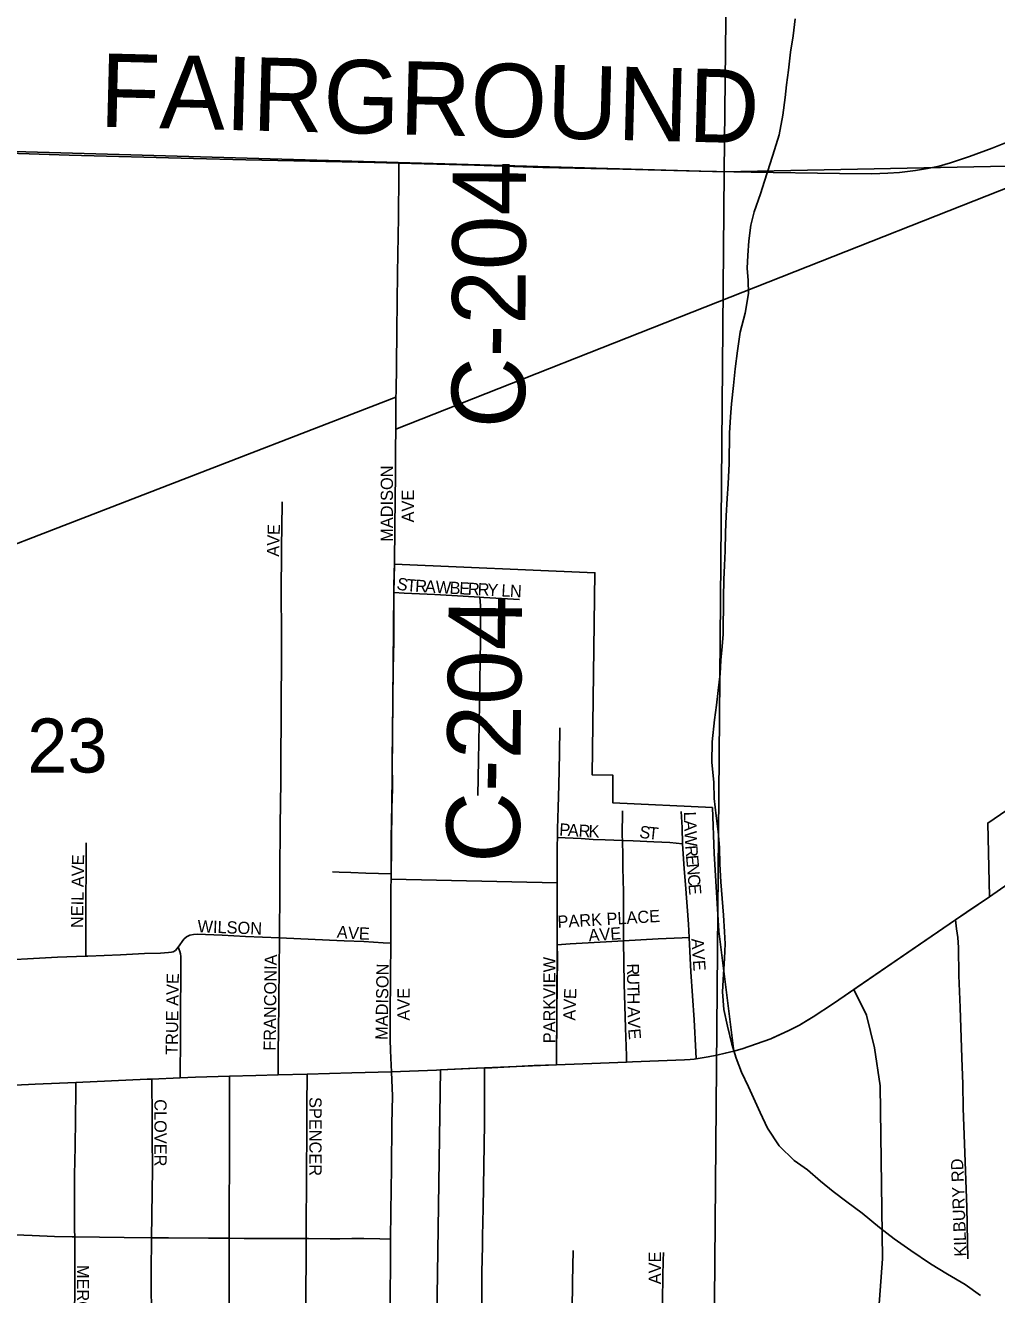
# Model space of a CAD drawing. Extents: x 1584893 to 1934202, y 663575 to 1091909.
# Drawn here: x 1800974 to 1804945, y 942980 to 948170 of the extents above; entities that cross this region are included whole.
import ezdxf

# ---------------------------------------------------------------- set-up
doc = ezdxf.new("R2010")
doc.units = 0
for name, color, linetype in [('GM_X_City_Street', 7, 'Continuous'), ('GM_X_City_Street_Text', 7, 'Continuous'), ('GM_X_Corporation', 7, 'Continuous'), ('GM_X_County_Road', 7, 'Continuous'), ('GM_X_County_Road_Text', 7, 'Continuous'), ('GM_X_Minor_River', 7, 'Continuous'), ('GM_X_Section', 7, 'Continuous'), ('GM_X_Section_Text', 7, 'Continuous'), ('GM_X_State_Route', 7, 'Continuous'), ('GM_X_Township_Subdivision', 7, 'Continuous'), ('GM_X_Township_Subdivision_Text', 7, 'Continuous')]:
    doc.layers.add(name, color=color, linetype=linetype)

msp = doc.modelspace()

# ---------------------------------------------------------------- linework, layer by layer
at = {"layer": 'GM_X_City_Street'}
for points in [[(1802482.4, 945967), (1802484.7, 946120.6), (1802487.3, 946335.9), (1802487.1, 946435.3), (1802488.3, 946519.1)], [(1802012.7, 944438.7), (1802013, 944462.1), (1802013.4, 944614.7), (1802013.7, 944704), (1802016.1, 944899.8), (1802017.6, 945076.3), (1802018.8, 945232.8), (1802019.3, 945280.4), (1802019.8, 945340), (1802019.2, 945393.3), (1802019.7, 945452.5), (1802020.2, 945525), (1802020.5, 945696.2), (1802019.9, 945840.2), (1802019.7, 945888.4), (1802020.7, 945982.1), (1802021.4, 946044.3), (1802022.2, 946114.3), (1802023.3, 946221.2)], [(1801220.2, 944363.7), (1801220.2, 944385.3), (1801220.4, 944415.1), (1801220.6, 944449), (1801220.8, 944492.6), (1801221.2, 944559), (1801221.5, 944626.8), (1801221.8, 944687), (1801222.1, 944737.5), (1801222.3, 944781.1), (1801222.6, 944827.4)], [(1802228.8, 944709.1), (1802256.4, 944707.5), (1802303.7, 944706.6), (1802365.1, 944704), (1802468.6, 944700.5)], [(1802467.3, 944417.3), (1802467.8, 944512), (1802467.8, 944574.3), (1802467.8, 944621.6), (1802468.6, 944700.5)], [(1801598, 944401.1), (1801621.8, 944433.2), (1801632.4, 944443.4), (1801645.6, 944449.6), (1801661, 944452.3), (1801676.9, 944453.5), (1801709.5, 944452.8), (1801778.6, 944449.4), (1801873.3, 944444.9), (1802012.7, 944438.7)], [(1802007.1, 943878.3), (1802007.3, 943916.9), (1802007.5, 943948), (1802007.6, 943966.5), (1802008.1, 944065.9), (1802009.3, 944160.8), (1802010, 944221.1), (1802010.8, 944280.4), (1802011.7, 944352.3), (1802012.2, 944396), (1802012.7, 944438.7)], [(1802012.7, 944438.7), (1802217.5, 944429.3), (1802277.5, 944426.9), (1802357.3, 944423.4), (1802436.2, 944419), (1802467.3, 944417.3)], [(1802470.5, 943891.6), (1802469.1, 943918.4), (1802466.9, 943978.2), (1802465.3, 944022.7), (1802465.2, 944113.8), (1802466.9, 944285.7), (1802467.3, 944417.3)], [(1801220.2, 944363.7), (1801229, 944364.1), (1801362.3, 944368.8), (1801460.5, 944374.9), (1801526, 944376.9), (1801559.4, 944378.7), (1801570.8, 944379.8), (1801577.8, 944381.5), (1801587.4, 944387.8), (1801592.7, 944393.9), (1801598, 944401.1)], [(1801606.7, 943866.2), (1801606.9, 943907.1), (1801607.4, 943994.5), (1801607.7, 944046), (1801608, 944113.1), (1801608.4, 944185), (1801608.8, 944243.4), (1801609, 944294.9), (1801609.3, 944336.7), (1801609.4, 944362.1), (1801607.6, 944373.8), (1801605.1, 944382.9), (1801600.7, 944394.1), (1801598, 944401.1)], [(1800931.6, 944350.1), (1800982.9, 944352.7), (1801104.7, 944359.7), (1801220.2, 944363.7)], [(1801179.9, 943847.9), (1801179.6, 943812.8), (1801177, 943584.5), (1801175.1, 943470), (1801174.8, 943341.1), (1801175.2, 943245.2), (1801175.4, 943215.9)], [(1801489.5, 943212.5), (1801490.5, 943303), (1801492.8, 943496), (1801492, 943620.5), (1801492.4, 943685.9), (1801492.4, 943734.5), (1801490.8, 943827), (1801490.1, 943861.3)], [(1801806.7, 943210.3), (1801807.4, 943353.3), (1801807.7, 943506.1), (1801807.8, 943569.5), (1801807.9, 943652), (1801808.3, 943833.1), (1801808.4, 943872.7)], [(1802125.3, 943881.8), (1802125.2, 943852), (1802124.8, 943779), (1802124.3, 943693.1), (1802123.9, 943591.5), (1802123.6, 943534.2), (1802123, 943419.6), (1802121.8, 943288.1), (1802121.8, 943271.7), (1802122.1, 943209)], [(1802467, 943207), (1802468.1, 943319.1), (1802470.5, 943498.5), (1802472.6, 943677.9), (1802474.4, 943791.9), (1802470.5, 943891.6)], [(1800829.3, 943229.2), (1801001.3, 943221.1), (1801093.2, 943217), (1801165, 943216.1), (1801175.4, 943215.9)], [(1801175.4, 943215.9), (1801175.7, 943180.5), (1801175.9, 943016.8), (1801174.5, 942886), (1801173.5, 942689.7), (1801172.3, 942559.6), (1801171.3, 942463.8), (1801170.6, 942382.7), (1801168.5, 942314.6)], [(1801175.4, 943215.9), (1801378.1, 943213.6), (1801489.5, 943212.5)], [(1801482.9, 942294.7), (1801482.9, 942300.6), (1801483.2, 942332.4), (1801486.3, 942676.2), (1801489.4, 942938), (1801488.3, 942987.2), (1801488.3, 943085.6), (1801489.3, 943200.3), (1801489.5, 943212.5)], [(1801489.5, 943212.5), (1801558.3, 943211.9), (1801722.1, 943211.5), (1801806.7, 943210.3)], [(1801800.9, 942275.1), (1801801.6, 942348.8), (1801803.9, 942589.5), (1801805.3, 942802.3), (1801806.4, 943031.4), (1801806.5, 943173.6), (1801806.7, 943210.3)], [(1801806.7, 943210.3), (1801868.4, 943209.2), (1801918.3, 943209.7), (1801967.1, 943209.3), (1802122.1, 943209)], [(1802122.1, 943209), (1802122.1, 943189.8), (1802121.7, 943156.9), (1802121.8, 943124.1), (1802121.4, 943074.8), (1802120.9, 943043.6), (1802120, 942971.6), (1802119.8, 942923.8), (1802119.4, 942867.4), (1802119.2, 942829.2), (1802118.9, 942762.5), (1802118, 942532.3), (1802116.8, 942422.8), (1802116.1, 942384.6), (1802114.8, 942317.8), (1802113.4, 942262.2), (1802113.1, 942251.9)], [(1802122.1, 943209), (1802130.6, 943209), (1802219.9, 943208.7), (1802260, 943208.7), (1802308.4, 943208.9), (1802357.1, 943209.2), (1802422.7, 943207.9), (1802467, 943207)], [(1802455.2, 942220.6), (1802456.3, 942285.9), (1802457.6, 942363), (1802458.3, 942477.3), (1802460.1, 942591.4), (1802460.9, 942671.8), (1802461.1, 942734.1), (1802461.6, 942749.5), (1802463.4, 942879), (1802465.6, 942976.5), (1802466.2, 943106.9), (1802467, 943207)]]:
    msp.add_lwpolyline(points, dxfattribs=at)
at = {"layer": 'GM_X_Corporation'}
for points in [[(1800456.1, 945864.7), (1802488.6, 946649.4), (1802488.3, 946519.1), (1805222.2, 947597.8)], [(1805012.7, 944979.3), (1804908.7, 944908.4), (1804915.8, 944607.2), (1804776.9, 944512.7), (1804277.6, 944170), (1804195.2, 944115.6), (1804166.8, 944098.9), (1804138.5, 944082.2), (1804094.8, 944059.4), (1804030.3, 944029.7), (1804021.1, 944025.4), (1803962.8, 944005.1), (1803904.4, 943984.7), (1803870.9, 943975.3), (1803808.8, 944465.8), (1803789.5, 944784.1), (1803782.7, 944971.5), (1803375.3, 944991.1), (1803375.6, 945103.5), (1803291.5, 945104.8), (1803302.1, 945931.7), (1802482.3, 945967), (1802480.7, 945850.9), (1802469.4, 944679.3), (1803147.3, 944663.8), (1803148.2, 944410.3), (1803145.2, 943920.2), (1802850.8, 943906.8), (1802671.4, 943898.9), (1802646.7, 942233.9)]]:
    msp.add_lwpolyline(points, dxfattribs=at)
at = {"layer": 'GM_X_County_Road'}
for points in [[(1802501.2, 947606), (1802809.9, 947597.9), (1803088.7, 947589.4), (1803416.9, 947582.6), (1803728.6, 947573.8), (1803941.8, 947569.7), (1804302.8, 947564.2), (1804434, 947563.3), (1804499.4, 947565.2), (1804548.3, 947568.6), (1804613.2, 947576.5), (1804661.5, 947584.5), (1804709.3, 947595), (1804756.6, 947607.9), (1804834.3, 947633.3), (1804926.5, 947667.5), (1805185.3, 947771.7)], [(1799836.2, 947683), (1800250.7, 947669.5), (1800595.1, 947657.6), (1800988.9, 947645), (1801152.8, 947639.2), (1801661.5, 947625.6), (1801874.7, 947619.8), (1802137.2, 947614.3), (1802399.7, 947608.7), (1802501.2, 947606)], [(1802488.6, 946649.5), (1802489.1, 946670.9), (1802490.6, 946779.1), (1802492.1, 946922.1), (1802494.6, 947156.3), (1802498.6, 947386.1), (1802500.6, 947560.7), (1802501.2, 947606)], [(1802488.3, 946519.1), (1802488.8, 946569.7), (1802488.8, 946639.6), (1802488.6, 946649.5)], [(1802480.7, 945850.9), (1802480.7, 945870.8), (1802481.6, 945936.9), (1802482.4, 945967)], [(1802468.6, 944700.5), (1802468.6, 944758.4), (1802469.5, 944831.2), (1802471.2, 944927.7), (1802474.2, 945047.6), (1802473.7, 945162.7), (1802474.6, 945278.5), (1802476.3, 945409.2), (1802478.1, 945537.2), (1802479.8, 945653.9), (1802480.7, 945788.5), (1802480.7, 945850.9)], [(1803891.7, 941145.1), (1803928.3, 941217.2), (1803997.2, 941317), (1804082, 941418.3), (1804141.9, 941520.2), (1804178.7, 941604.2), (1804203.7, 941699.2), (1804215.1, 941797.4), (1804218, 941909.9), (1804219.7, 942007.6), (1804214.9, 942210.2), (1804224.2, 942350.1), (1804253.3, 942479.3), (1804311.7, 942589.7), (1804403, 942735.4), (1804458.4, 942867.1), (1804477.6, 943126.6), (1804468.5, 943833.4), (1804445.6, 943988.5), (1804413.1, 944123), (1804361.2, 944227.4)]]:
    msp.add_lwpolyline(points, dxfattribs=at)
at = {"layer": 'GM_X_Minor_River'}
for points in [[(1803916.1, 946993.2), (1803930.4, 947073.1), (1803928.6, 947127.2), (1803924.8, 947177.2), (1803927, 947229.2), (1803931.2, 947289.3), (1803939.5, 947353.3), (1803953.7, 947407.2), (1803980, 947481.2), (1803996.2, 947533.2), (1804018.5, 947605.1), (1804036.7, 947661.1), (1804055, 947723), (1804071.3, 947803), (1804079.6, 947875), (1804085.8, 947927), (1804094, 947987), (1804102.3, 948061), (1804112.5, 948127), (1804120.8, 948197.1)], [(1804879.5, 942977.1), (1804815.6, 943021.4), (1804743.7, 943063.7), (1804673.8, 943106), (1804594, 943160.3), (1804526.1, 943208.6), (1804466.2, 943254.9), (1804394.4, 943313.2), (1804332.5, 943359.4), (1804276.6, 943401.7), (1804224.8, 943443.9), (1804170.9, 943490.1), (1804117, 943528.4), (1804055.2, 943588.6), (1804007.4, 943660.9), (1803977.6, 943725), (1803930, 943829.2), (1803902.2, 943889.4), (1803880.4, 943947.5), (1803862.6, 944003.6), (1803844.9, 944077.7), (1803829.1, 944145.8), (1803823.4, 944217.9), (1803827.7, 944289.9), (1803831.9, 944353.9), (1803834.2, 944414), (1803832.3, 944464), (1803828.6, 944532.1), (1803817.1, 944668.2), (1803813.4, 944740.2), (1803811.6, 944808.3), (1803805.9, 944874.3), (1803798.1, 944938.4), (1803790.4, 945008.5), (1803788.6, 945074.5), (1803780.9, 945156.6), (1803781.3, 945240.7), (1803791.6, 945330.7), (1803799.9, 945390.7), (1803806.1, 945450.7), (1803814.3, 945518.7), (1803816.6, 945574.7), (1803822.8, 945630.7), (1803827, 945680.7), (1803827.5, 945828.8), (1803829.8, 945904.8), (1803832.1, 945960.9), (1803834.3, 946020.9), (1803836.6, 946096.9), (1803838.8, 946165), (1803843.1, 946235), (1803847.3, 946295), (1803851.7, 946379), (1803852.1, 946503.1), (1803856.4, 946569.1), (1803860.6, 946623.1), (1803868.9, 946697.2), (1803875.2, 946765.2), (1803885.4, 946839.2), (1803895.7, 946915.2), (1803916.1, 946993.2)]]:
    msp.add_lwpolyline(points, dxfattribs=at)
at = {"layer": 'GM_X_Section'}
for points in [[(1798546, 953053.1), (1803891.8, 953170.2), (1803831.3, 947571.5), (1798501.2, 947724.3)], [(1803891.8, 953170.2), (1809287.5, 952939), (1809214, 947834.3), (1809209.1, 947678.4), (1803831.3, 947571.5)], [(1803831.3, 947571.5), (1803783.9, 942158.7), (1798488.5, 942423.4), (1798501.2, 947724.3)], [(1809209.1, 947678.4), (1809163.3, 942525.6), (1803783.9, 942158.7), (1803831.3, 947571.5)]]:
    msp.add_lwpolyline(points, close=True, dxfattribs=at)
at = {"layer": 'GM_X_State_Route'}
for points in [[(1804915.8, 944607.2), (1805023.7, 944681.7)], [(1803870.9, 943975.3), (1803904.4, 943984.8), (1804021.1, 944025.4), (1804094.8, 944059.4), (1804138.5, 944082.2), (1804195.1, 944115.6), (1804277.6, 944170), (1804361.2, 944227.4), (1804375, 944236.9), (1804776.9, 944512.7), (1804820.4, 944542.6), (1804915.8, 944607.2)], [(1803145.2, 943920.2), (1803325.1, 943926.3), (1803431.6, 943930.7), (1803455.9, 943931.7), (1803668.4, 943940.3), (1803691.1, 943941.9), (1803708.1, 943943.4), (1803715.7, 943944.4), (1803740.3, 943947.7), (1803765.3, 943951.7), (1803800.6, 943959.1), (1803835.5, 943966.8), (1803870.9, 943975.3)], [(1800931, 943836.8), (1801013.3, 943840.8), (1801179.9, 943847.9), (1801472.2, 943860.5), (1801490.1, 943861.3), (1801606.7, 943866.2), (1801668.7, 943868.9), (1801808.4, 943872.7), (1801915.3, 943875.6), (1802007.1, 943878.3), (1802125.3, 943881.8), (1802308.9, 943887.2), (1802470.5, 943891.6), (1802654.9, 943898.1), (1802671.4, 943898.9)], [(1802671.4, 943898.9), (1802785.4, 943904.2), (1802850.8, 943906.8), (1802880.4, 943908), (1803054.2, 943917), (1803145.2, 943920.2)]]:
    msp.add_lwpolyline(points, dxfattribs=at)
at = {"layer": 'GM_X_Township_Subdivision'}
for points in [[(1802480.7, 945850.9), (1802522.1, 945848.8), (1802647.6, 945842.3), (1802717.5, 945839.1), (1802832.2, 945831.6)], [(1802824, 945020.4), (1802825.9, 945165.9), (1802829.3, 945312.6), (1802833, 945573.7), (1802834.4, 945654), (1802835, 945716.4), (1802834.4, 945764.4), (1802834.1, 945796.8), (1802832.2, 945831.6)], [(1802832.2, 945831.6), (1802847.6, 945830.6), (1802993.9, 945822.8)], [(1803149.2, 944849.3), (1803149.9, 944885.2), (1803152.5, 944971.4), (1803154.4, 945062.9), (1803157.3, 945193), (1803158.9, 945297.5)], [(1803414.8, 944837.4), (1803413.9, 944855.9), (1803415.2, 944958.8)], [(1803660.7, 944823.3), (1803658.7, 944889.7), (1803654.4, 944955.3)], [(1803147.3, 944663.8), (1803148.6, 944816.6), (1803149.2, 944849.3)], [(1803149.2, 944849.3), (1803180.5, 944847.3), (1803246, 944844.5), (1803295, 944841.7), (1803344, 944839.5), (1803414.8, 944837.4)], [(1803419.3, 944426.9), (1803419.2, 944545.9), (1803418.8, 944578), (1803418.8, 944627.1), (1803416.8, 944725.1), (1803415.8, 944774.2), (1803414.8, 944837.4)], [(1803414.8, 944837.4), (1803458.4, 944836), (1803543.2, 944832), (1803608.6, 944828.1), (1803660.7, 944823.3)], [(1803687.3, 944440.8), (1803684.4, 944495.2), (1803673, 944657.7), (1803667.9, 944721.4), (1803660.7, 944823.3)], [(1803148.2, 944410.3), (1803147.3, 944663.8)], [(1804827.1, 943125.9), (1804823.2, 943338.2), (1804813.3, 943597), (1804808.3, 943742.5), (1804806, 943840.2), (1804802.8, 943947.9), (1804796.2, 944153.7), (1804790.9, 944285.1), (1804788.3, 944399.4), (1804785.7, 944440.6), (1804781.3, 944476.2), (1804776.9, 944512.7)], [(1803148.2, 944410.3), (1803200.5, 944414.2), (1803347.9, 944423.1), (1803419.3, 944426.9)], [(1803419.3, 944426.9), (1803561.1, 944434.3), (1803658.8, 944439.3), (1803687.3, 944440.8)], [(1803431.6, 943930.7), (1803430.8, 943956.2), (1803427.3, 944070.4), (1803422, 944250.5), (1803419.3, 944426.9)], [(1803715.7, 943944.4), (1803714.3, 943973), (1803707.7, 944103.2), (1803694.8, 944299.4), (1803687.3, 944440.8)], [(1803145.2, 943920.2), (1803146.8, 944132.4), (1803149.3, 944359.3), (1803148.2, 944410.3)], [(1802842.4, 943177.8), (1802843.3, 943219), (1802844.9, 943334), (1802850.5, 943679.3), (1802851.2, 943745.1), (1802850.9, 943843.8), (1802850.8, 943863.5), (1802850.8, 943906.8)], [(1802833.4, 942401.2), (1802833.3, 942430.8), (1802834.8, 942529.4), (1802834.4, 942578.8), (1802835.9, 942627.8), (1802838.2, 942792.2), (1802838.3, 942825.1), (1802839.9, 942989.4), (1802840.5, 943038.8), (1802840.2, 943071.8), (1802842.4, 943177.8)], [(1803205.1, 942393.7), (1803205.5, 942428), (1803208, 942671.6), (1803209.9, 942913.3), (1803211.2, 943032.9), (1803213.7, 943159.9)], [(1803561.9, 942408.7), (1803570.4, 942423), (1803573, 942437.1), (1803574.9, 942468.8), (1803576.7, 942647.4), (1803578.9, 942956.4), (1803580.1, 943053.8), (1803580.8, 943119), (1803582.4, 943151.6)]]:
    msp.add_lwpolyline(points, dxfattribs=at)

# ---------------------------------------------------------------- texts
at = {"layer": 'GM_X_City_Street_Text'}
for s, rotation, p in [('MADISON', 90, (1802476.6, 946058.3)), ('AVE', 90, (1802562.7, 946137.5)), ('V', 87.9324, (1802011.9, 946041)), ('E', 88.323, (1802013.5, 946085.4)), ('A', 87.9234, (1802010.3, 945997.1)), ('NEIL AVE', 89.1065, (1801209.5, 944478.5)), ('WILSON', 357.8737, (1801677, 944461.7)), ('A', 354.3068, (1802245.5, 944439.6)), ('V', 356.863, (1802291.7, 944435.1)), ('E', 357.2782, (1802336.1, 944432.6)), ('FRANCONIA', 89.3024, (1801997.1, 943976.9)), ('MADISON', 89.118, (1802454.7, 944021.3)), ('TRUE AVE', 89.1777, (1801596.6, 943959.8)), ('AVE', 90, (1802545.1, 944100.3)), ('CLOVER', 270, (1801501.1, 943779.1)), ('SPENCER', 270, (1802134.7, 943787.9)), ('MERCHANT', 270, (1801184.3, 943101.5))]:
    msp.add_text(s, height=50, rotation=rotation, dxfattribs=at).set_placement(p)
at = {"layer": 'GM_X_County_Road_Text'}
for s, rotation, p in [('FAIRGROUND', 358.5316, (1801275.4, 947756)), ('C-204', 89.724, (1803016.1, 946522.1)), ('C-204', 89.4594, (1802994.1, 944743.9))]:
    msp.add_text(s, height=300, rotation=rotation, dxfattribs=at).set_placement(p)
at = {"layer": 'GM_X_Section_Text'}
msp.add_text('23', height=221, rotation=0, dxfattribs=at).set_placement((1800981.3, 945114.8))
at = {"layer": 'GM_X_Township_Subdivision_Text'}
for s, rotation, p in [('S', 348.2239, (1802488.8, 945864.9)), ('T', 355.7348, (1802530.4, 945856.7)), ('R', 356.6891, (1802566.4, 945854)), ('A', 356.784, (1802606, 945851.8)), ('W', 356.7835, (1802649.9, 945849.3)), ('B', 356.7966, (1802707, 945846.1)), ('E', 356.802, (1802746.6, 945843.9)), ('R', 356.7932, (1802781.7, 945841.9)), ('R', 357.76, (1802822.2, 945839.7)), ('Y', 357.0263, (1802861.6, 945838.1)), ('L', 356.993, (1802918.7, 945835.1)), ('N', 356.9826, (1802953.8, 945833.3)), ('L', 271.9401, (1803665.9, 944954.2)), ('P', 356.5276, (1803155.5, 944857.7)), ('A', 356.5474, (1803190.6, 944855.5)), ('R', 356.558, (1803234.5, 944852.9)), ('K', 358.0675, (1803275.5, 944850.4)), ('S', 352.1635, (1803481.9, 944848.8)), ('T', 354.1484, (1803518.6, 944843.8)), ('A', 271.9538, (1803667, 944919)), ('W', 272.4661, (1803668.5, 944874.6)), ('R', 274.5668, (1803671.1, 944815.4)), ('E', 274.9694, (1803674.3, 944775.5)), ('N', 274.9669, (1803677.4, 944740.5)), ('C', 274.9613, (1803681.2, 944696.6)), ('E', 274.9569, (1803684.6, 944657.2)), ('PARK PLACE', 3.3645, (1803150.8, 944479.3)), ('AVE', 3.9434, (1803277.7, 944424.2)), ('AVE', 273.9431, (1803696.6, 944435.4)), ('PARKVIEW', 90, (1803141, 944007.9)), ('R', 270.9714, (1803432.7, 944333.7)), ('U', 270.9953, (1803433.3, 944294)), ('E', 87.5128, (1803225.2, 944187.7)), ('T', 270.9835, (1803434.1, 944250.1)), ('H', 270.9618, (1803434.7, 944214.9)), ('V', 87.7697, (1803223.5, 944143.8)), ('A', 270.9618, (1803435.7, 944157.6)), ('A', 88.929, (1803222.7, 944100.1)), ('V', 271.8296, (1803436.4, 944112.8)), ('E', 274.9694, (1803438, 944065.8)), ('KILBURY RD', 92.0442, (1804821.8, 943136.4)), ('AVE', 90, (1803572.2, 943022.3))]:
    msp.add_text(s, height=50, rotation=rotation, dxfattribs=at).set_placement(p)

doc.saveas('drawing.dxf')
